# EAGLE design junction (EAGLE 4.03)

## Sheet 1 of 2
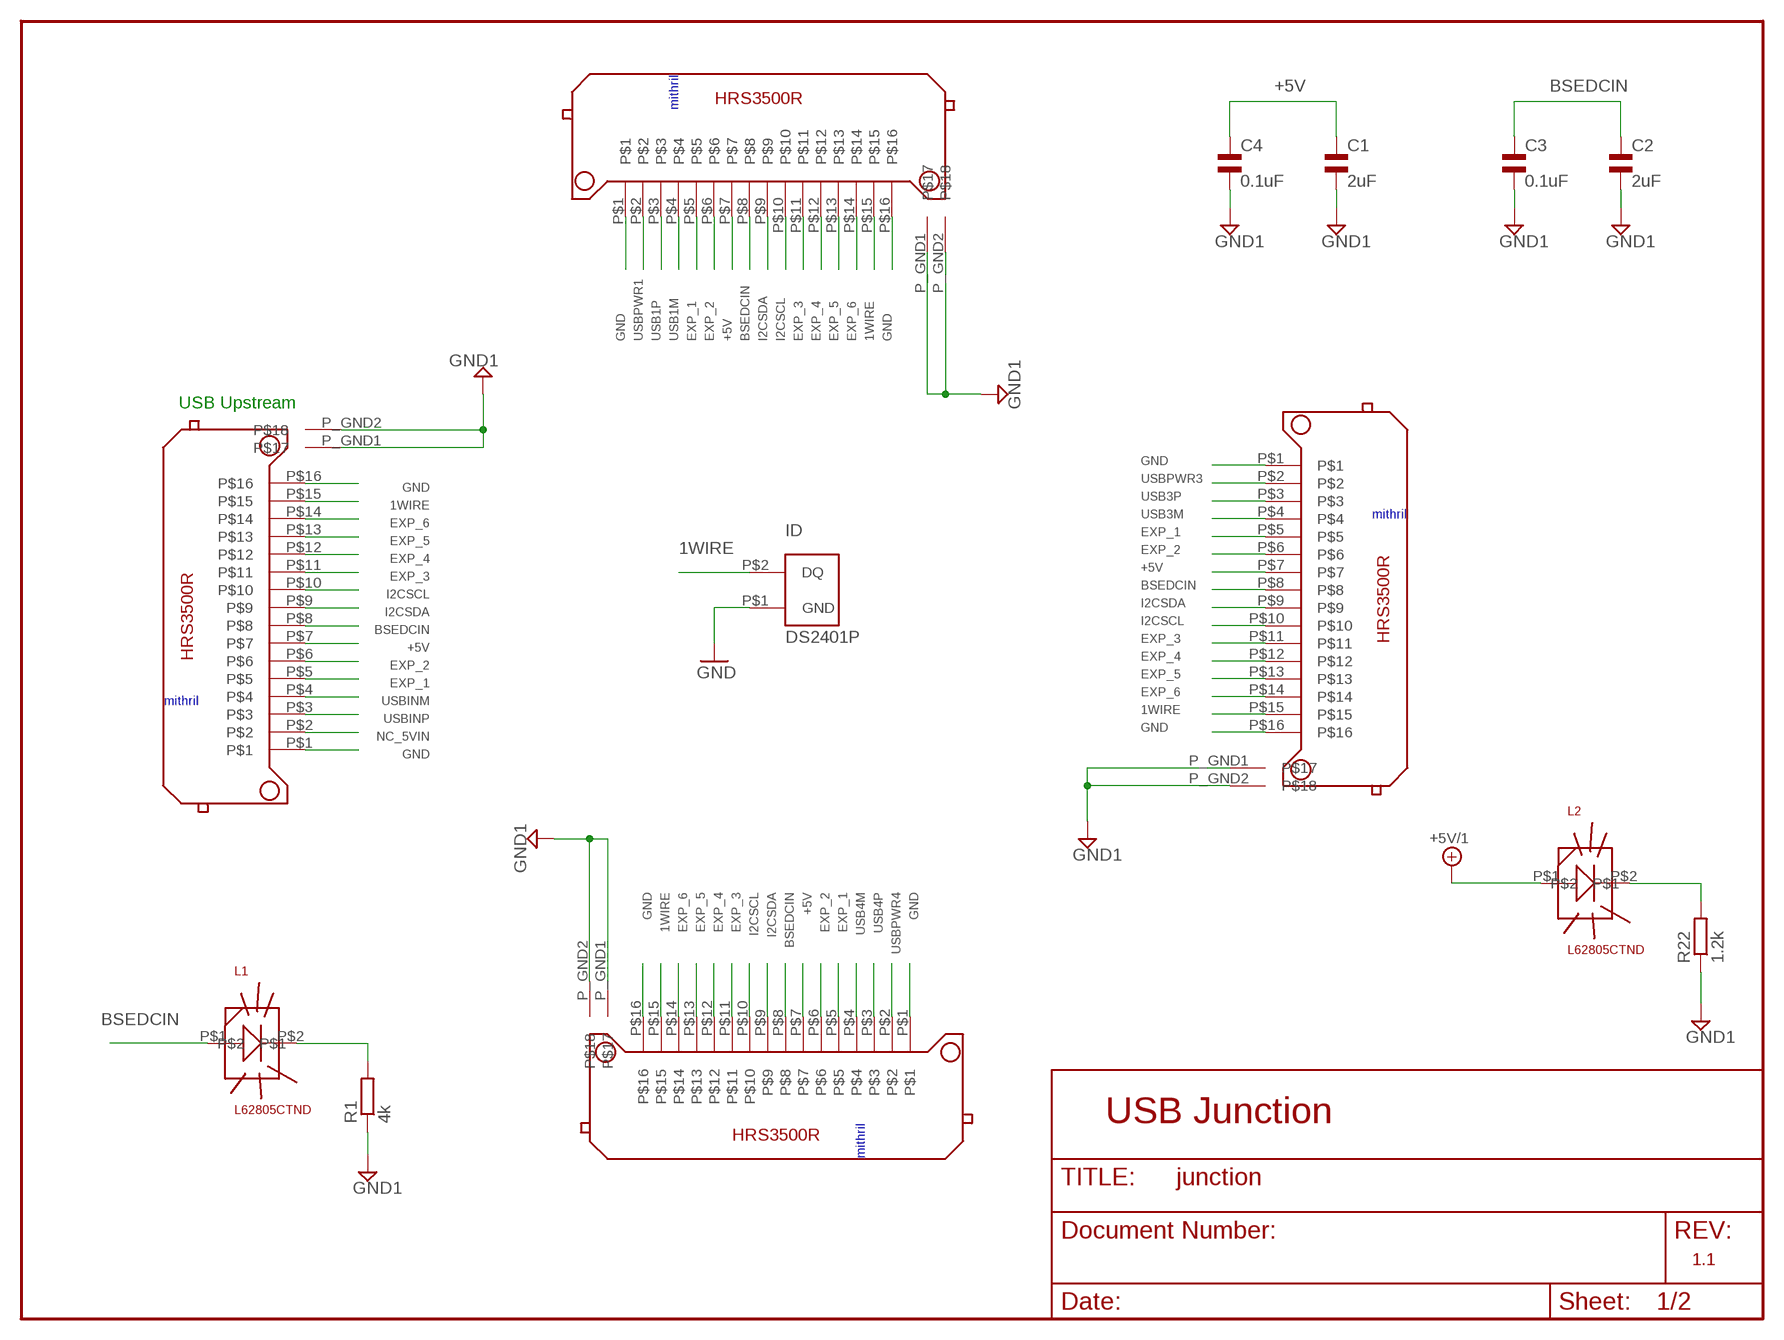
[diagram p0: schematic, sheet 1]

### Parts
C1  2uF  C1206  [C1206]
C2  2uF  C1206  [C1206]
C3  0.1uF  C1206  [C1206]
C4  0.1uF  C1206  [C1206]
ID  DS2401P  [TSOC6]
L1  L62805CTND  L62711CTND  [L62711CT]
L2  L62805CTND  L62711CTND  [L62711CT]
R1  4k  R1206  [R1206]
R22  1.2k  R1206  [R1206]
U6  HRS3500R  [HRS3500]
U7  HRS3500R  [HRS3500]
U8  HRS3500R  [HRS3500]
U9  HRS3500R  [HRS3500]

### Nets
1WIRE: ID.P$2(DQ) U6.P$15 U7.P$15 U8.P$15 U9.P$15 ; also sheet 2
+5V: C1.2 C4.2 L2.P$1 U6.P$7 U7.P$7 U8.P$7 U9.P$7 ; supply symbol labelled +5V/1 ; also sheet 2
BSEDCIN: C2.2 C3.2 L1.P$1 U6.P$8 U7.P$8 U8.P$8 U9.P$8
EXP_1: U6.P$5 U7.P$5 U8.P$5 U9.P$5
EXP_2: U6.P$6 U7.P$6 U8.P$6 U9.P$6
EXP_3: U6.P$11 U7.P$11 U8.P$11 U9.P$11
EXP_4: U6.P$12 U7.P$12 U8.P$12 U9.P$12
EXP_5: U6.P$13 U7.P$13 U8.P$13 U9.P$13
EXP_6: U6.P$14 U7.P$14 U8.P$14 U9.P$14
GND: C1.1 C2.1 C3.1 C4.1 ID.P$1(GND) R1.1 R22.1 U6.P$1 U6.P$16 U6.P_GND1 U6.P_GND2 U7.P$1 U7.P$16 U7.P_GND1 U7.P_GND2 U8.P$1 U8.P$16 U8.P_GND1 U8.P_GND2 U9.P$1 U9.P$16 U9.P_GND1 U9.P_GND2 ; supply symbol labelled GND1 ; also sheet 2
I2CSCL: U6.P$10 U7.P$10 U8.P$10 U9.P$10
I2CSDA: U6.P$9 U7.P$9 U8.P$9 U9.P$9
N$1: L1.P$2 R1.2
N$28: L2.P$2 R22.2
NC_5VIN: U6.P$2
USB1M: U7.P$4 ; also sheet 2
USB1P: U7.P$3 ; also sheet 2
USB3M: U8.P$4 ; also sheet 2
USB3P: U8.P$3 ; also sheet 2
USB4M: U9.P$4 ; also sheet 2
USB4P: U9.P$3 ; also sheet 2
USBINM: U6.P$4 ; also sheet 2
USBINP: U6.P$3 ; also sheet 2
USBPWR1: U7.P$2 ; also sheet 2
USBPWR3: U8.P$2 ; also sheet 2
USBPWR4: U9.P$2 ; also sheet 2

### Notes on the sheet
- mithril
- USB Upstream
- mithril
- mithril
- mithril | USB Junction
- 1.1

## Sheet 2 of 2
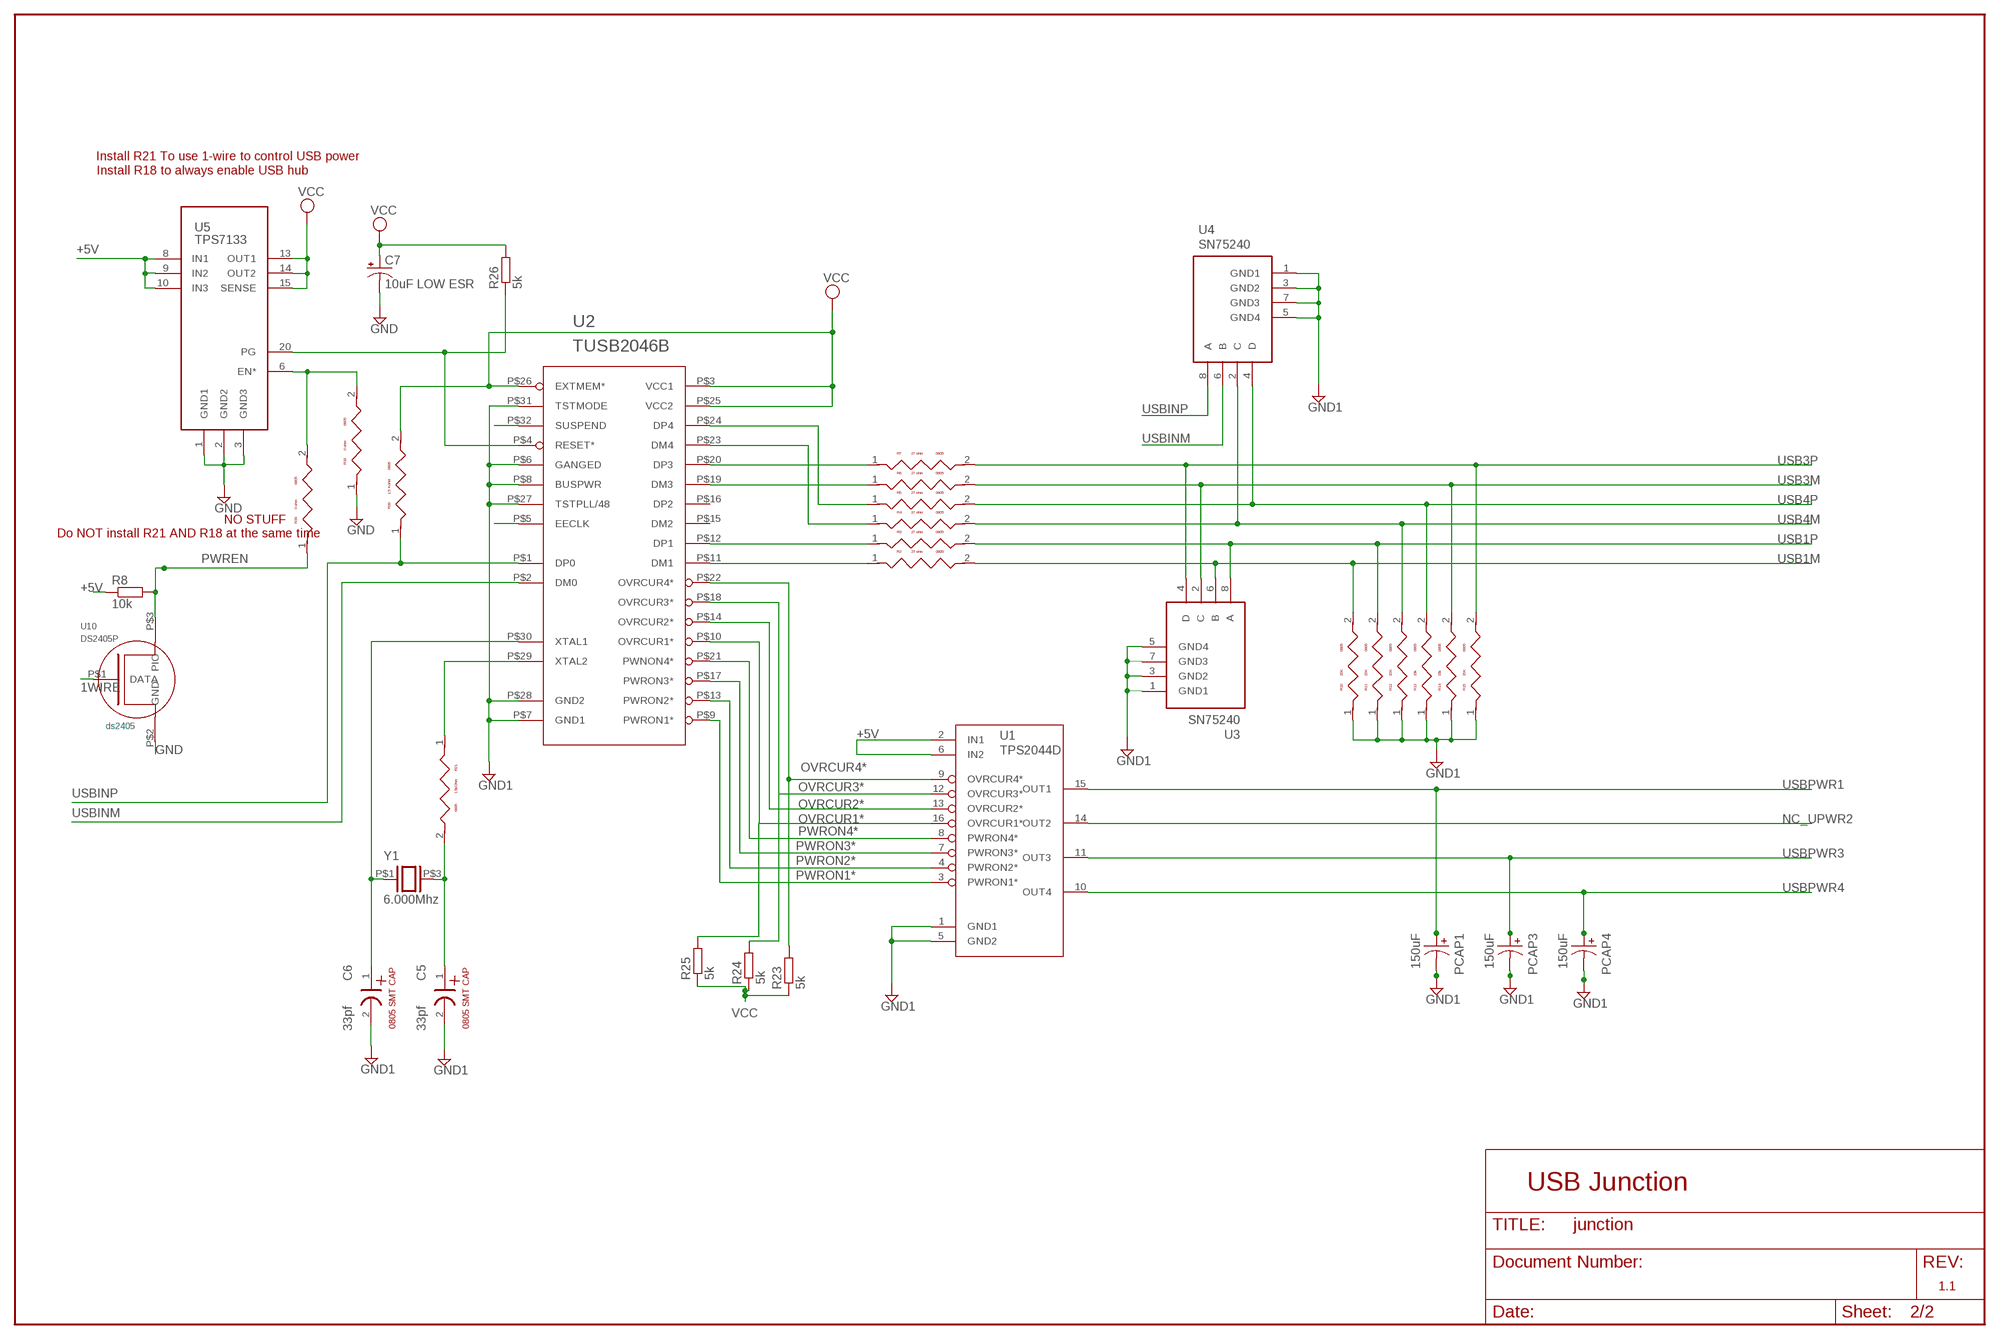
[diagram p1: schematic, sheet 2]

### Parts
C5  33pf  CAP-0805  [0805]
C6  33pf  CAP-0805  [0805]
C7  10uF LOW ESR  CPOL-USCT6032  [CT6032]
PCAP1  150uF  SPCAP0  [SPCAP]
PCAP3  150uF  SPCAP0  [SPCAP]
PCAP4  150uF  SPCAP0  [SPCAP]
R2  27 ohm  R-0805  [0805]
R3  27 ohm  R-0805  [0805]
R4  27 ohm  R-0805  [0805]
R5  27 ohm  R-0805  [0805]
R6  27 ohm  R-0805  [0805]
R7  27 ohm  R-0805  [0805]
R8  10k  R1206  [R1206]
R10  15K  R-0805@2  [0805]
R11  15K  R-0805@2  [0805]
R12  15K  R-0805@2  [0805]
R13  15k  R-0805@2  [0805]
R14  15k  R-0805@2  [0805]
R15  15K  R-0805@2  [0805]
R18  0 ohm  R-0805@2  [0805]
R19  0 ohm  R-0805@2  [0805]
R20  1.5 Kohm  R-0805@2  [0805]
R21  1.5kOhm  R-0805@2  [0805]
R23  5k  R0805  [R0805]
R24  5k  R0805  [R0805]
R25  5k  R0805  [R0805]
R26  5k  R0805  [R0805]
U1  TPS2044D  TPS2044A  [SOP-16]
U2  TUSB2046B  [TQFP-32]
U3  SN75240  [SSOP08DB]
U4  SN75240  [SSOP08DB]
U5  TPS7133  [TSSOP020]
U10  DS2405P  [TSOC6]
Y1  6.000Mhz  XTAL/SMDM505SMD  [M505]

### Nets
1WIRE: U10.P$1(DATA) ; also sheet 1
+5V: R8.1 U1.2(IN1) U1.6(IN2) U5.8(IN1) U5.9(IN2) U5.10(IN3) ; also sheet 1
GND: C5.2 C6.2 C7.- PCAP1.P$2(-) PCAP3.P$2(-) PCAP4.P$2(-) R10.1 R11.1 R12.1 R13.1 R14.1 R15.1 R18.1 U1.1(GND1) U1.5(GND2) U2.P$6(GANGED) U2.P$7(GND1) U2.P$8(BUSPWR) U2.P$27(TSTPLL/48) U2.P$28(GND2) U2.P$31(TSTMODE) U3.1(GND1) U3.3(GND2) U3.5(GND4) U3.7(GND3) U4.1(GND1) U4.3(GND2) U4.5(GND4) U4.7(GND3) U5.1(GND1) U5.2(GND2) U5.3(GND3) U10.P$2(GND) ; supply symbol labelled GND1 ; also sheet 1
N$2: R2.1 U2.P$11(DM1)
N$3: R3.1 U2.P$12(DP1)
N$6: R6.1 U2.P$19(DM3)
N$7: R7.1 U2.P$20(DP3)
N$18: R26.1 U2.P$4(RESET*) U5.20(PG)
N$20: R18.2 R19.2 U5.6(EN*)
NC_EECLK: U2.P$5(EECLK)
NC_SPND: U2.P$32(SUSPEND)
NC_UPWR2: U1.14(OUT2)
OVRCUR1*: R25.2 U1.16(OVRCUR1*) U2.P$10(OVRCUR1*)
OVRCUR2*: U1.13(OVRCUR2*) U2.P$14(OVRCUR2*)
OVRCUR3*: R24.2 U1.12(OVRCUR3*) U2.P$18(OVRCUR3*)
OVRCUR4*: R23.2 U1.9(OVRCUR4*) U2.P$22(OVRCUR4*)
PWREN: R8.2 R19.1 U10.P$3(PIO)
PWRON1*: U1.3(PWRON1*) U2.P$9(PWRON1*)
PWRON2*: U1.4(PWRON2*) U2.P$13(PWRON2*)
PWRON3*: U1.7(PWRON3*) U2.P$17(PWRON3*)
PWRON4*: U1.8(PWRON4*) U2.P$21(PWNON4*)
USB1M: R2.2 R10.2 U3.6(B) ; also sheet 1
USB1P: R3.2 R11.2 U3.8(A) ; also sheet 1
USB3M: R6.2 R14.2 U3.2(C) ; also sheet 1
USB3P: R7.2 R15.2 U3.4(D) ; also sheet 1
USB4M: R4.2 R12.2 U4.2(C) ; also sheet 1
USB4OM: R4.1 U2.P$23(DM4)
USB4P: R5.2 R13.2 U4.4(D) ; also sheet 1
USBINM: U2.P$2(DM0) U4.6(B) ; also sheet 1
USBINP: R20.1 U2.P$1(DP0) U4.8(A) ; also sheet 1
USBO4P: R5.1 U2.P$24(DP4)
USBPWR1: PCAP1.P$1(+) U1.15(OUT1) ; also sheet 1
USBPWR3: PCAP3.P$1(+) U1.11(OUT3) ; also sheet 1
USBPWR4: PCAP4.P$1(+) U1.10(OUT4) ; also sheet 1
VCC: C7.+ R20.2 R23.1 R24.1 R25.1 R26.2 U2.P$3(VCC1) U2.P$25(VCC2) U2.P$26(EXTMEM*) U5.13(OUT1) U5.14(OUT2) U5.15(SENSE)
XTAL1: C6.1 U2.P$30(XTAL1) Y1.P$1
XTAL2: R21.1 U2.P$29(XTAL2)
XTAL2_R: C5.1 R21.2 Y1.P$3
Unconnected: U2.P$15(DM2) U2.P$16(DP2)

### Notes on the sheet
- Install R21 To use 1-wire to control USB power
- Install R18 to always enable USB hub
- NO STUFF
- Do NOT install R21 AND R18 at the same time
- USB Junction
- 1.1

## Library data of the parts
C1-C4 = IPC-RCL:C1206
C5 C6 = smd:CAP-0805
C7 = rcl:CPOL-US: POLARIZED CAPACITOR, American symbol
ID = evilb0rg:DS2401P
L1 L2 = evilb0rg@2:L62711CTND
PCAP1 PCAP3 PCAP4 = evilb0rg:SPCAP: Panasonic Speciality Polymer Aluminum Electrolytic Capacitor
R1 R22 = ipc-rcl@2:R1206
R2-R7 = smd:R-0805
R8 = IPC-RCL:R1206
R10-R15 R18-R21 = smd:R-0805@2
R23-R26 = IPC-RCL:R0805
U1 = smb-junc:TPS2044A
U2 = smd:TUSB2046B
U3 U4 = smb-junc:SN75240
U5 = smb-junc:TPS7133
U6-U9 = evilb0rg:HRS3500R
U10 = evilb0rg:DS2405P
Y1 = special:XTAL/SMD

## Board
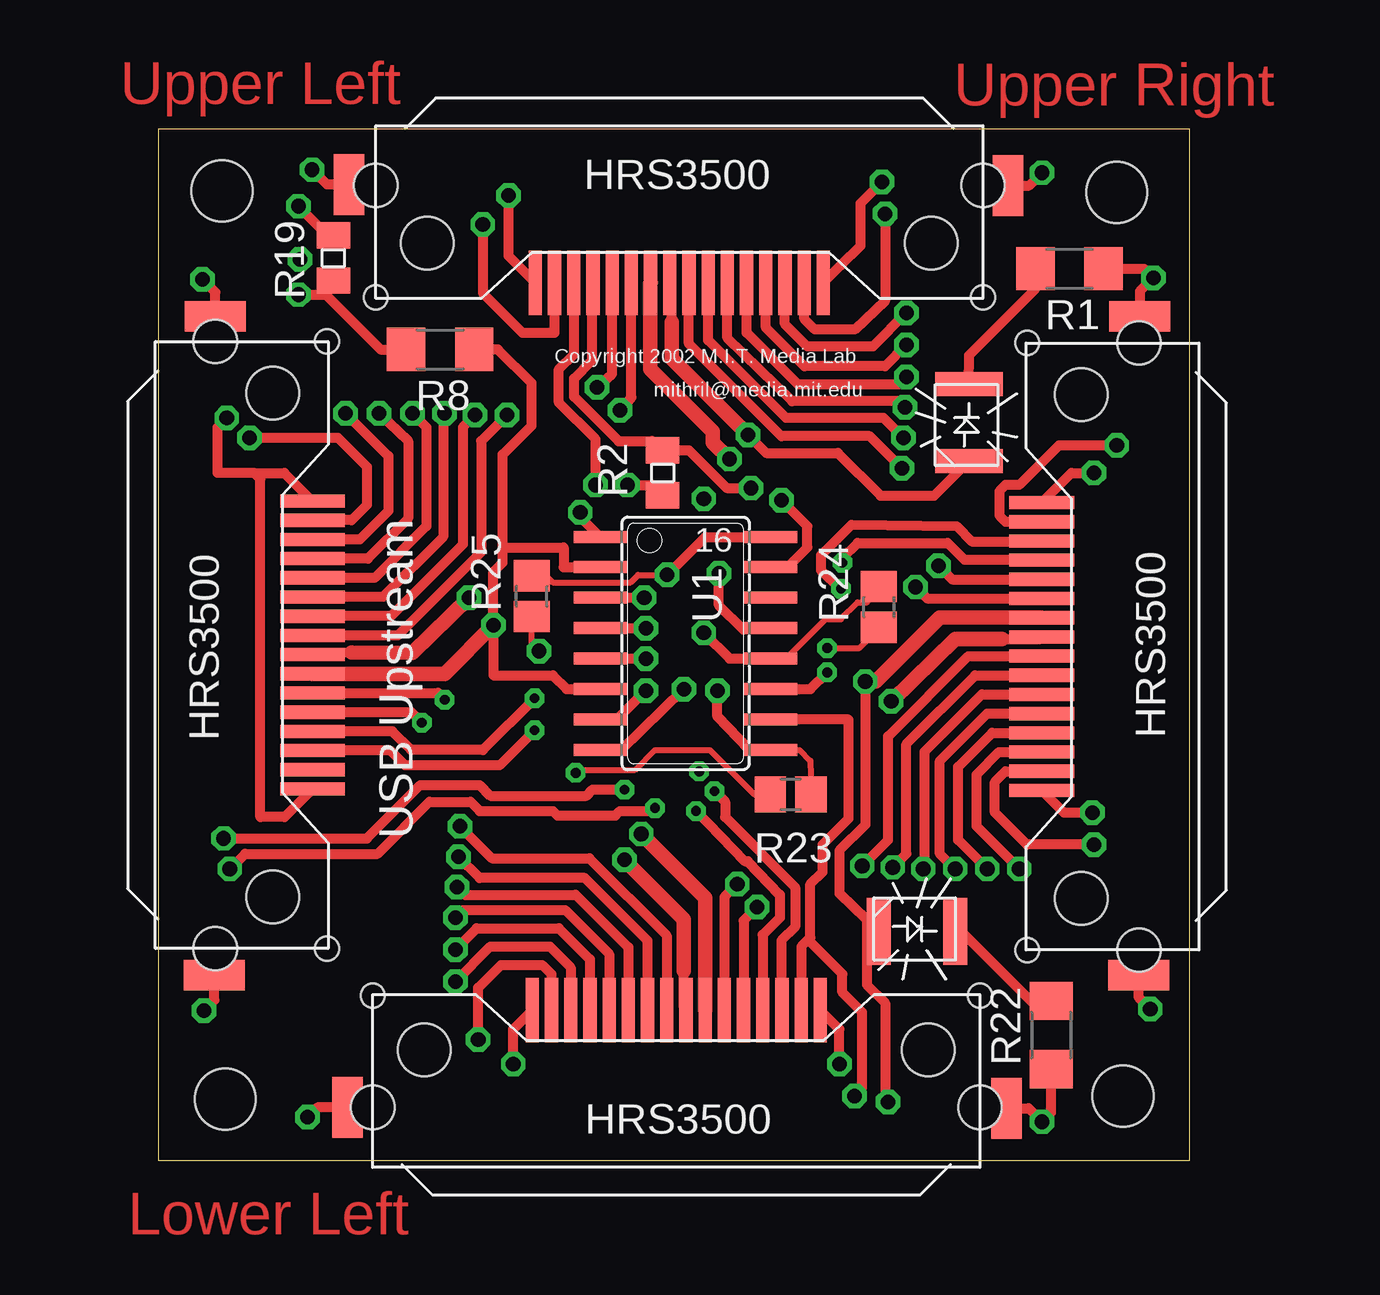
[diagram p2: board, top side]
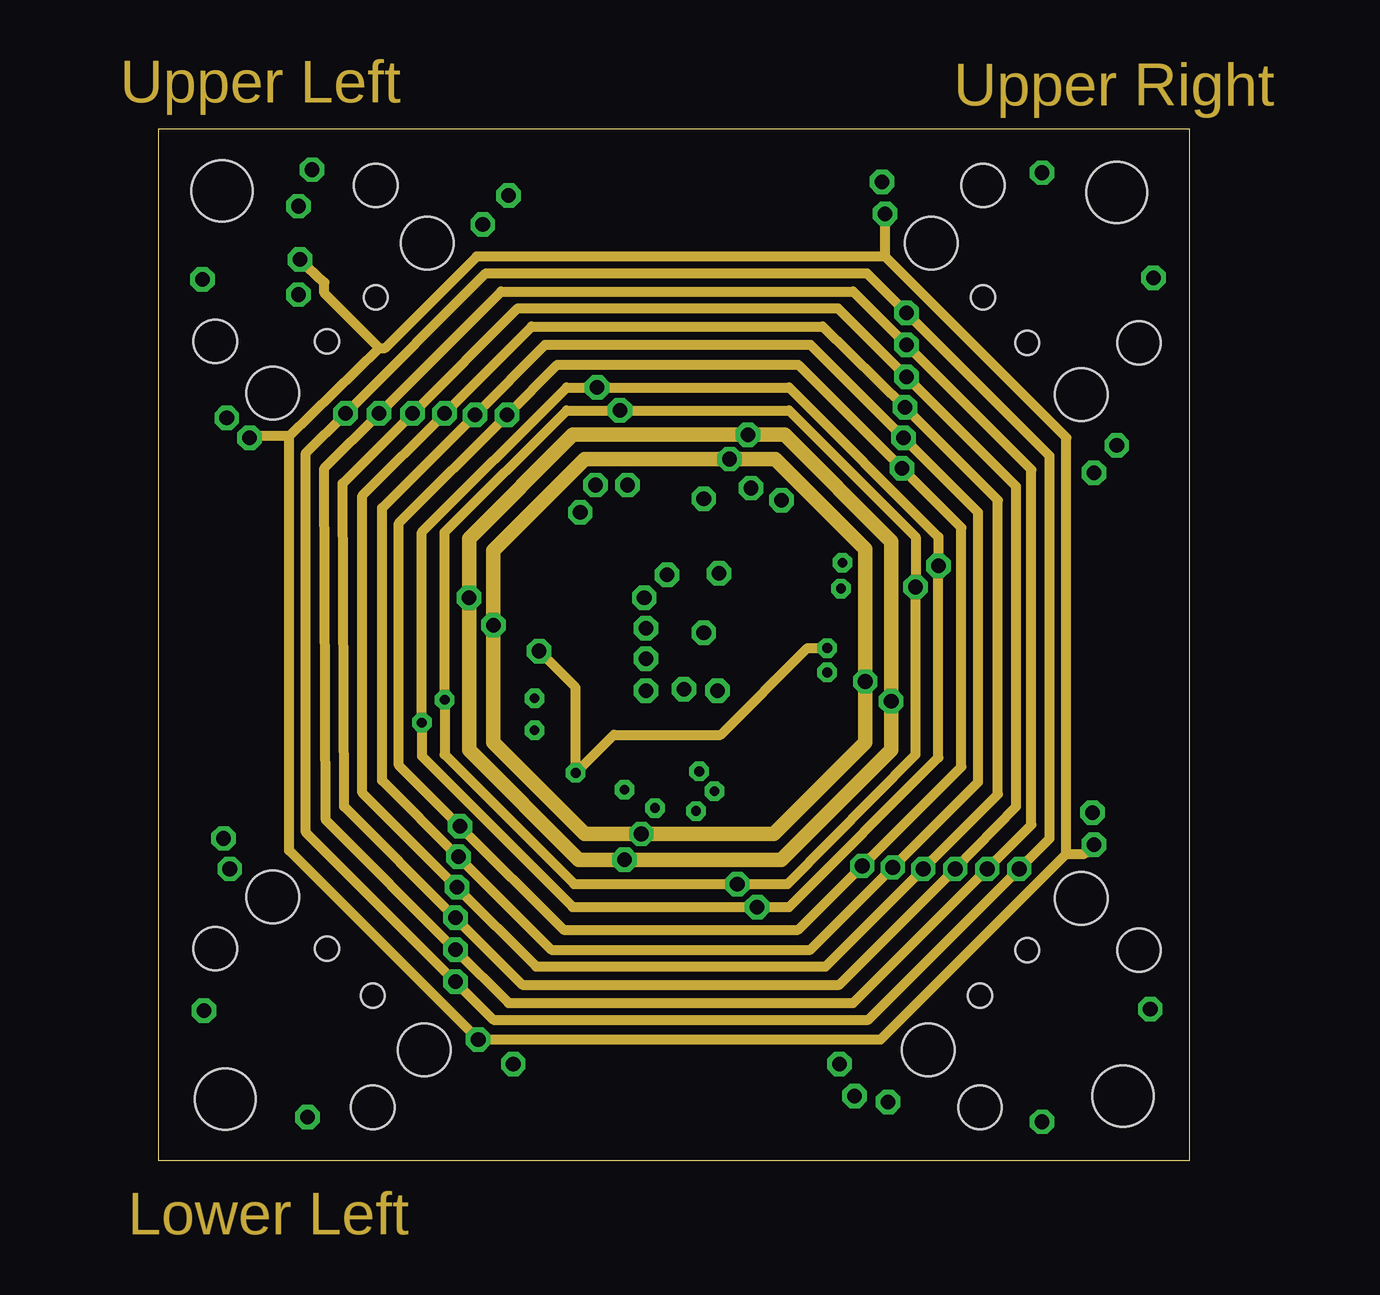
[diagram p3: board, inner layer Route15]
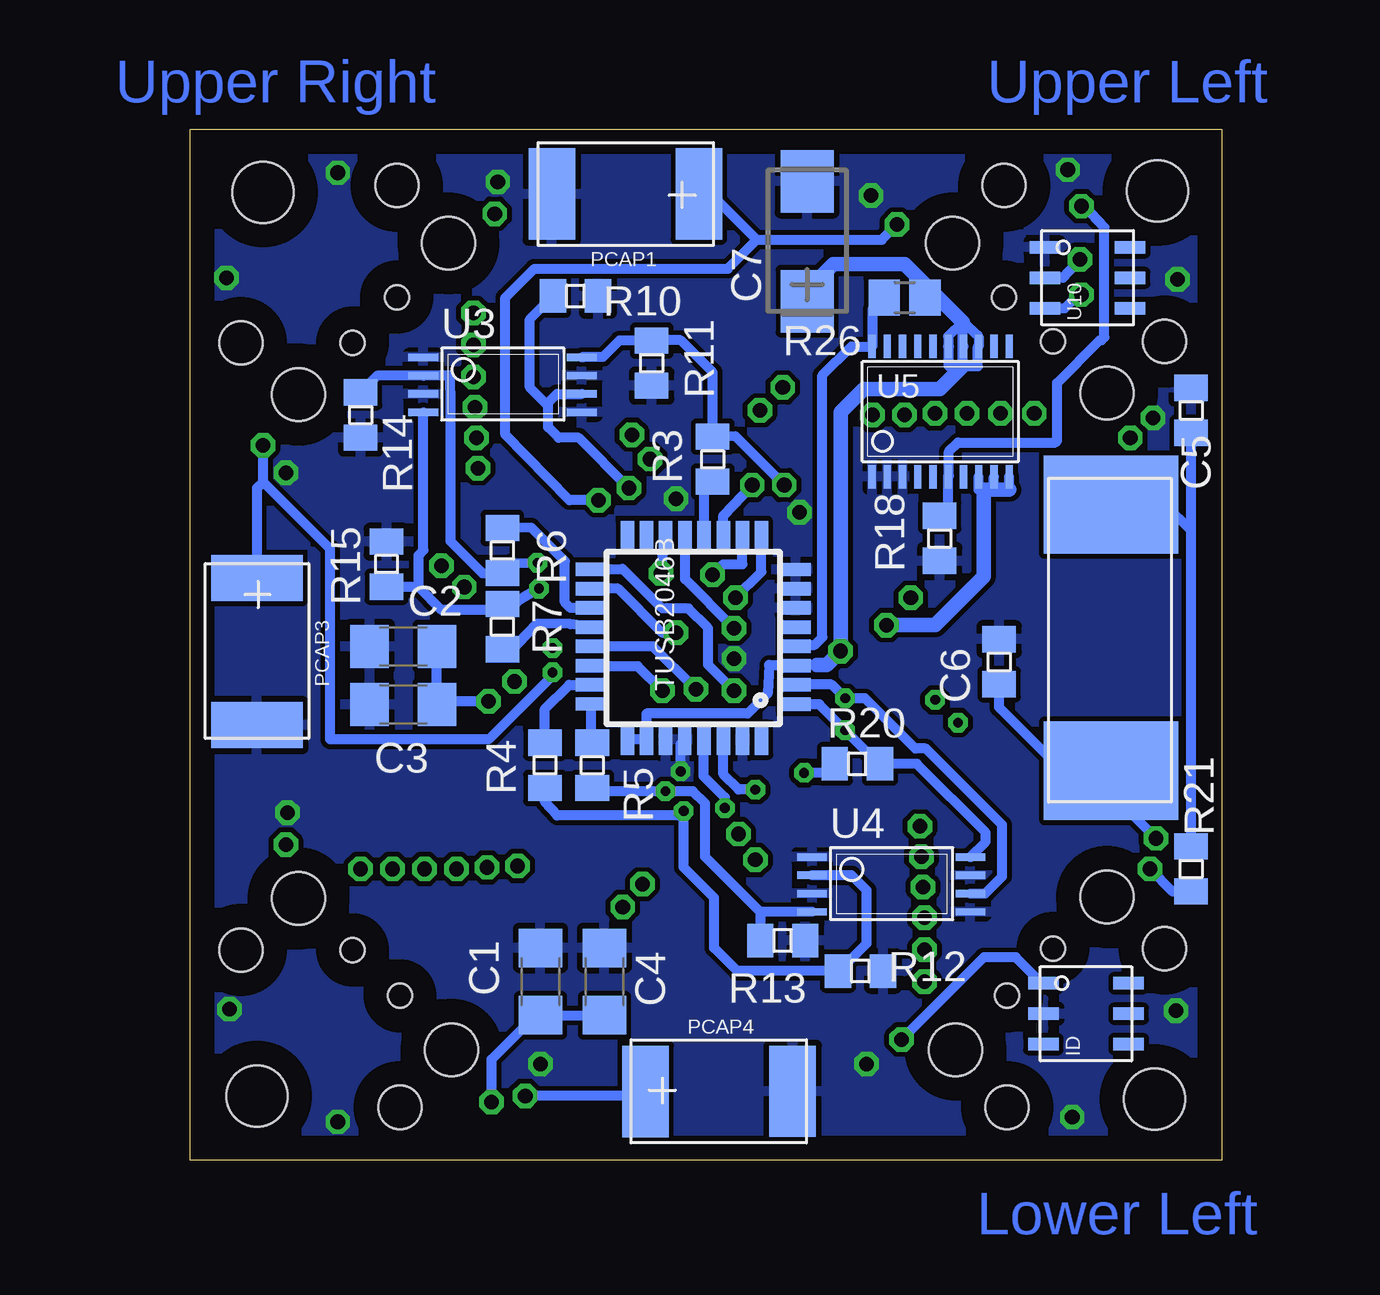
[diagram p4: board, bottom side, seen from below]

Size 42.97 x 42.98 mm. Coordinates in mm from the lower left corner, seen from the top.
Outline: 0,0 42.97,0 42.97,42.98 0,42.98 0,0
Copper layers used: Top, Route15, Bottom
Holes 2.54 mm at 2.79,2.57 40.19,2.69 39.94,40.35 2.66,40.41

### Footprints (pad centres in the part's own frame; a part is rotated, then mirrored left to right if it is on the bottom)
C1206 = smd 1.6 x 1.8: 1 -1.4,0; 2 1.4,0
0805 = smd 1.092 x 1.397: 1 -0.94,0; 2 0.94,0
CT6032 = smd 2.6 x 2.2: + -2.5,0; - 2.5,0
TSOC6 = smd 0.508 x 1.27: P$1 0,1.778; P$2 1.27,1.778; P$3 -1.27,1.778; P$4 0,-1.778; P$5 -1.27,-1.778; P$6 1.27,-1.778
L62711CT = smd 1 x 2.8: P$1 -1.6,0; P$2 1.6,0
SPCAP = smd 1.93 x 3.81: P$1 -3.047,-0.007; P$2 3.079,0
R1206 = smd 1.6 x 1.803: 1 -1.422,0; 2 1.422,0
R0805 = smd 1.3 x 1.5: 1 -0.85,0; 2 0.85,0
SOP-16 = smd 0.5 x 2.2: 1 -4.445,-3.556; 2 -3.175,-3.556; 3 -1.905,-3.556; 4 -0.635,-3.556; 5 0.635,-3.556; 6 1.905,-3.556; 7 3.175,-3.556; 8 4.445,-3.556; 9 4.445,3.556; 10 3.175,3.556; 11 1.905,3.556; 12 0.635,3.556; 13 -0.635,3.556; 14 -1.905,3.556; 15 -3.175,3.556; 16 -4.445,3.556
TQFP-32 = smd 1.27 x 0.56: P$1 4.66,-2.655; P$2 4.66,-1.85; P$3 4.66,-1.05; P$4 4.66,-0.245; P$5 4.66,0.55; P$6 4.66,1.36; P$7 4.66,2.155; P$8 4.66,2.955; P$17 -3.86,2.96; P$18 -3.86,2.155; P$19 -3.86,1.355; P$20 -3.86,0.55; P$21 -3.86,-0.245; P$22 -3.86,-1.055; P$23 -3.86,-1.85; P$24 -3.86,-2.65 | smd 0.56 x 1.27: P$9 3.24,4.34; P$10 2.45,4.34; P$11 1.65,4.34; P$12 0.855,4.34; P$13 0.055,4.34; P$14 -0.75,4.34; P$15 -1.555,4.335; P$16 -2.345,4.345; P$25 -2.34,-4.135; P$26 -1.55,-4.135; P$27 -0.75,-4.135; P$28 0.045,-4.135; P$29 0.845,-4.135; P$30 1.65,-4.135; P$31 2.455,-4.13; P$32 3.245,-4.14
SSOP08DB = smd 0.305 x 1.245: 1 -1.067,-3.48; 2 -0.305,-3.48; 3 0.457,-3.48; 4 1.219,-3.48; 5 1.219,3.124; 6 0.457,3.124; 7 -0.305,3.124; 8 -1.067,3.124
TSSOP020 = smd 0.305 x 0.991: 1 -2.819,-2.896; 2 -2.184,-2.896; 3 -1.549,-2.896; 4 -0.914,-2.896; 5 -0.279,-2.896; 6 0.356,-2.896; 7 0.991,-2.896; 8 1.626,-2.896; 9 2.261,-2.896; 10 2.896,-2.896; 11 2.896,2.54; 12 2.261,2.54; 13 1.626,2.54; 14 0.991,2.54; 15 0.356,2.54; 16 -0.279,2.54; 17 -0.914,2.54; 18 -1.549,2.54; 19 -2.184,2.54; 20 -2.819,2.54
HRS3500 = smd 0.55 x 2.7: P$1 6,1.35; P$2 5.2,1.35; P$3 4.4,1.35; P$4 3.6,1.35; P$5 2.8,1.35; P$6 2,1.35; P$7 1.2,1.35; P$8 0.4,1.35; P$9 -0.4,1.35; P$10 -1.2,1.35; P$11 -2,1.35; P$12 -2.8,1.35; P$13 -3.6,1.35; P$14 -4.4,1.35; P$15 -5.2,1.35; P$16 -6,1.35 | smd 1.27 x 2.54: P_GND1 -13.7,-2.7; P_GND2 13.76,-2.74 | hole 2.2: -10.5,-0.3; 10.5,-0.3 | hole 1.8: -12.65,-2.7; 12.65,-2.7 | hole 1: -12.65,1.95; 12.65,1.95
M505 = smd 4.1 x 5.6: P$1 5.5,-0.1; P$3 -5.6,-0.1

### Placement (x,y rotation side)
C1  28.38,7.46 270 bottom
C2  34.09,21.42 0 bottom
C3  34.09,19.01 0 bottom
C4  25.71,7.46 270 bottom
C5  1.27,31.27 90 bottom
C6  9.27,20.79 90 bottom
C7  17.27,38.32 90 bottom
ID  5.65,6.12 90 bottom
L1  33.78,30.76 90 top
L2  31.62,9.55 0 top
PCAP1  24.82,40.28 180 bottom
PCAP3  40.19,21.23 270 bottom
PCAP4  20.95,2.88 0 bottom
R1  37.97,37.17 180 top
R2  21.01,28.66 90 top
R3  21.2,29.24 90 bottom
R4  28.19,16.47 270 bottom
R5  26.22,16.47 270 bottom
R6  29.97,25.43 270 bottom
R7  29.97,22.25 90 bottom
R8  11.74,33.81 180 top
R10  26.92,36.03 180 bottom
R11  23.74,33.24 90 bottom
R12  15.04,7.9 180 bottom
R13  18.28,9.17 180 bottom
R14  35.87,31.08 90 bottom
R15  34.79,24.85 270 bottom
R18  11.74,25.93 90 bottom
R19  7.3,37.62 90 top
R20  15.17,16.54 180 bottom
R21  1.27,12.15 90 bottom
R22  37.21,5.23 90 top
R23  26.35,15.27 0 top
R24  30.03,23.08 90 top
R25  15.55,23.52 90 top
R26  13.2,35.97 0 bottom
U1  21.97,21.55 270 top
U2  22.41,21.68 0 bottom
U3  29.78,32.41 270 bottom
U4  13.58,11.58 270 bottom
U5  11.74,31.39 0 bottom
U6  5.08,21.49 270 top
U7  21.71,37.94 180 top
U8  38.16,21.42 90 top
U9  21.58,4.92 0 top
U10  5.58,36.79 90 bottom
Y1  4.5,21.74 270 bottom

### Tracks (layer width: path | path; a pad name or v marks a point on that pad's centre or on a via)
1WIRE  (via drill 0.61)
  Top 0.406: U6.P$15 8.05,26.69 8.7,27.33 8.7,28.92 7.49,30.12 v3.8,30.12 | v30.28,39.46 30.28,35.84 29.01,34.63 27.36,34.63 26.92,35.08 26.92,36.6 26.91,36.59 U7.P$15 | v38.98,13.17 36.19,13.17 34.86,14.5 34.86,15.77 35.3,16.22 36.76,16.22 36.77,16.22 U8.P$15 | v13.33,5.04 13.33,7.2 14.28,8.15 16,8.15 16.38,7.77 16.38,6.25 U9.P$15
  Route15 0.406: 5.46,30.19 9.2,33.87 | 9.2,33.87 9.46,33.87 13.27,37.68 30.28,37.68 | 30.28,37.68 37.84,30.12 37.84,12.79 | 37.84,12.79 30.09,5.04 v13.33,5.04 5.46,12.92 5.46,30.19 | v38.98,13.17 38.6,12.79 37.84,12.79 | 30.28,37.68 v30.28,39.46 | 5.46,30.19 3.87,30.19 v3.8,30.12 | 9.2,33.87 6.92,36.16 6.92,36.6 v5.9,37.55
  Bottom 0.406: ID.P$2 7.49,7.39 8.57,8.47 9.9,8.47 v13.33,5.04 | v5.9,37.55 6.6,36.79 U10.P$1
+5V  (via drill 0.61)
  Top 0.406: U1.6 17.01,19.65 16.44,20.22 13.97,20.22 v13.97,22.31 13.97,24.54 14.35,24.92 14.35,25.55 | 14.35,25.55 16.89,25.55 16.89,24.73 U1.2 | 28.38,11.13 L2.P$1 | 28.38,11.13 28.38,12.92 29.46,14 v29.46,19.96 | 28.38,11.13 28.39,11.13 29.52,10.06 29.52,7.33 30.28,6.57 30.28,2.57 v30.41,2.44 | R8.1 14.16,33.81 15.55,32.41 15.55,30.63 14.35,29.43 14.35,25.55
  Top 0.61: U6.P$7 11.93,20.29 v13.97,22.31 | U9.P$7 22.79,6.27 22.79,10.95 v20.12,13.61 | U8.P$7 36.8,22.63 32.57,22.63 29.9,19.96 v29.46,19.96 | U7.P$7 20.5,32.98 23.11,30.38 23.11,29.93 v23.81,29.24
  Route15 0.61: v13.97,22.31 13.97,25.43 17.77,29.24 v23.81,29.24 25.71,29.24 29.46,25.49 v29.46,19.96 29.46,17.42 25.65,13.61 v20.12,13.61 17.77,13.61 13.97,17.42 v13.97,22.31
  Bottom 0.406: 8.85,27.97 U5.10 | U5.8 10.12,27.97 9.9,27.97 9.48,27.97 U5.9 | v30.41,2.44 30.41,4.22 28.57,6.06 C1.2 C4.2
  Bottom 0.61: v13.97,22.31 11.93,22.31 9.9,24.35 9.9,27.97 8.85,27.97
BSEDCIN  (via drill 0.61)
  Top 0.406: 8.06,21.17 U6.P$8 | U7.P$8 21.31,36.56 21.39,36.47 21.39,34.95 | U8.P$8 36.83,21.81 36.76,21.74 35.17,21.74 | U9.P$8 21.98,6.29 21.9,6.38 21.9,7.9 | L1.P$1 32.33,27.71 30.09,27.71 28.32,29.49 25.33,29.49 v24.57,30.25
  Top 0.61: 8.06,21.17 10.58,21.15 v12.95,23.46 | v24.57,30.25 21.39,33.43 21.39,34.95 | v30.54,19.14 33.21,21.74 35.17,21.74 | v19.43,12.53 21.9,10.06 21.9,7.9
  Route15 0.61: v12.95,23.46 12.95,25.93 17.27,30.25 v24.57,30.25 26.09,30.25 30.54,25.81 v30.54,19.14 30.54,17.11 25.97,12.53 v19.43,12.53 17.52,12.53 12.95,17.11 v12.95,23.46
  Bottom 0.406: v30.54,19.14 32.51,19.14 32.63,19.01 C3.2 32.7,19.84 | 32.7,19.84 C2.2 | 32.7,19.84
EXP_1  (via drill 0.41, 0.61)
  Top 0.406: U6.P$5 10.54,18.69 v10.98,18.25 | U7.P$5 18.91,32.79 v18.28,32.22 | U8.P$5 33.07,24.22 v32.51,24.79 | U9.P$5 24.38,10 v24.95,10.57
  Route15 0.406: v10.98,18.25 10.98,26.19 17.01,32.22 v18.28,32.22 26.28,32.22 32.51,26 v32.51,24.79 32.51,16.79 26.28,10.57 v24.95,10.57 17.27,10.57 10.98,16.85 v10.98,18.25
EXP_2  (via drill 0.41, 0.61)
  Top 0.406: U6.P$6 11.65,19.49 v11.93,19.2 | U7.P$6 19.71,31.81 v19.23,31.27 | U8.P$6 32.03,23.42 v31.55,23.9 | U9.P$6 23.58,10.98 v24.12,11.52
  Route15 0.406: v11.93,19.2 11.93,26.19 17.01,31.27 v19.23,31.27 26.28,31.27 31.55,26 v31.55,23.9 31.55,16.92 26.22,11.52 v24.12,11.52 17.33,11.52 11.93,16.92 v11.93,19.2
EXP_3  (via drill 0.61)
  Top 0.406: U6.P$11 9.36,23.49 11.87,26 11.87,31.08 v11.93,31.14 | U7.P$11 23.71,34.28 26.41,31.65 30.86,31.65 v31.11,31.39 | U8.P$11 34.32,19.42 31.93,17.04 31.93,12.22 v31.87,12.15 | U9.P$11 19.58,8.88 17.39,11.07 12.76,11.07 v12.44,11.39
  Route15 0.406: v11.93,31.14 15.55,34.76 27.68,34.76 v31.11,31.39 34.98,27.52 34.98,15.27 v31.87,12.15 27.81,8.09 15.74,8.09 v12.44,11.39 8.5,15.33 8.5,27.71 v11.93,31.14
EXP_4  (via drill 0.61)
  Top 0.406: U6.P$12 9.02,24.29 11.17,26.44 11.17,30.57 v10.6,31.14 | U7.P$12 24.51,34.5 26.66,32.35 30.86,32.35 v31.17,32.66 | U8.P$12 34.53,18.63 32.57,16.66 32.57,12.79 v33.21,12.15 | U9.P$12 18.79,8.6 16.95,10.44 12.7,10.44 v12.38,10.12
  Route15 0.406: v10.6,31.14 14.98,35.52 28.32,35.52 v31.17,32.66 35.75,28.09 35.75,14.76 v33.21,12.15 28.38,7.33 15.17,7.33 v12.38,10.12 7.74,14.76 7.68,28.22 v10.6,31.14
EXP_5  (via drill 0.61)
  Top 0.406: U6.P$13 8.74,25.09 10.41,26.76 10.41,30 v9.2,31.14 | U7.P$13 25.31,34.72 26.92,33.11 30.28,33.11 v31.17,34 | U8.P$13 34.75,17.83 33.33,16.41 33.33,13.36 v34.54,12.15 | U9.P$13 17.98,8.39 16.7,9.68 13.27,9.68 v12.38,8.79
  Route15 0.406: v9.2,31.14 14.28,36.22 28.95,36.22 v31.17,34 36.38,28.79 36.38,14 v34.54,12.15 28.95,6.57 14.6,6.57 v12.38,8.79 6.98,14.19 6.92,28.85 v9.2,31.14
EXP_6  (via drill 0.61)
  Top 0.406: U6.P$14 8.4,25.89 9.58,27.08 9.58,29.36 v7.81,31.14 | U7.P$14 26.11,34.87 27.05,33.93 29.78,33.93 v31.17,35.33 | U8.P$14 35.03,17.03 34.1,16.09 34.1,13.93 v35.87,12.15 | U9.P$14 17.18,8.04 16.31,8.92 13.84,8.92 v12.38,7.45
  Route15 0.406: v7.81,31.14 13.65,36.98 29.52,36.98 v31.17,35.33 37.14,29.36 37.14,13.42 v35.87,12.15 29.59,5.87 13.97,5.87 v12.38,7.45 6.15,13.68 6.15,29.49 v7.81,31.14
GND  (via drill 0.41, 0.61)
  Top 0.406: U6.P_GND2 2.33,6.68 v1.9,6.25 | U9.P_GND1 6.63,2.21 v6.22,1.8 | U8.P$1 38.05,28.66 v38.98,28.66 | U8.P$16 37.73,14.5 v38.92,14.5 | U8.P_GND1 40.86,6.79 v41.33,6.31 | U9.P_GND2 36.26,2.17 v36.83,1.61 37.21,1.99 R22.1 | U9.P$1 28.38,5.47 v28.38,4.03 | U1.5 v20.31,20.92 | U8.P_GND2 40.9,36.23 v41.46,36.79 41.08,37.17 R1.1 | U7.P_GND1 36.29,40.64 v36.83,41.17 | U7.P$16 28.44,37.32 29.27,38.13 29.27,39.9 v30.16,40.79 | U7.P$1 14.6,37.7 v14.6,40.22 | U7.P_GND2 7.03,40.68 v6.41,41.3 | U6.P_GND1 2.38,36.19 v1.84,36.73 | U9.P$16 14.79,5.47 v14.79,4.03 | U6.P$16 5.25,28.66 4,28.66 | 4,28.66 2.47,28.66 2.47,30.57 v2.85,30.95 | 4,28.66 4.25,28.41 4.25,14.31 5.27,14.31 6.42,15.47 U6.P$1 | U1.1 17.58,26.82 v17.58,27.01
  Bottom 0.406: 22.35,17.54 22.35,17.55 | 22.35,17.54 U2.P$28 | v22.54,16.22 22.54,17.36 22.35,17.54
  other vias: 22.73,27.58
  pour Bottom: 0.25,42.7 0.25,0.28 42.73,0.28 42.73,42.7
I2CSCL  (via drill 0.61)
  Top 0.406: U6.P$10 9.7,22.69 12.7,25.68 12.7,30.57 v13.2,31.08 | U9.P$10 20.38,9.16 17.77,11.77 13.39,11.77 v12.5,12.66 | U8.P$10 34.04,20.22 31.17,17.36 31.17,12.79 v30.6,12.22 | U7.P$10 22.91,34.19 26.16,30.95 30.22,30.95 v31.05,30.12
  Route15 0.406: v13.2,31.08 16.12,34 27.17,34 v31.05,30.12 34.16,27.01 34.16,15.77 v30.6,12.22 27.17,8.79 16.38,8.79 v12.5,12.66 9.33,15.84 9.33,27.2 v13.2,31.08
I2CSDA  (via drill 0.61)
  Top 0.406: U6.P$9 9.98,21.89 13.46,25.36 13.46,30 v14.54,31.08 | U9.P$9 21.18,9.38 17.96,12.6 13.9,12.6 v12.57,13.93 | U7.P$9 22.11,34.04 25.97,30.19 29.65,30.19 v30.98,28.85 | U8.P$9 33.76,21.03 30.41,17.68 30.41,13.36 v29.33,12.28
  Route15 0.406: v14.54,31.08 16.63,33.17 26.66,33.17 v30.98,28.85 33.46,26.38 33.46,16.41 v29.33,12.28 26.66,9.61 16.89,9.61 v12.57,13.93 10.03,16.47 10.03,26.57 v14.54,31.08
N$1
  Top 0.406: L1.P$2 33.79,33.57 36.51,36.28 36.51,37.11 36.55,37.15 R1.2
N$2  (via drill 0.61)
  Top 0.406: R2.1 20.57,28.16 v19.55,28.16
  Bottom 0.406: U2.P$11 20.76,26.88 v19.55,28.16
N$3
  Bottom 0.406: U2.P$12 21.55,27.11 21.55,27.94 21.2,28.28 R3.1
N$6
  Bottom 0.406: U2.P$19 27.13,23.03 27.36,23.27 27.36,24.98 28.76,26.38 R6.1
N$7
  Bottom 0.406: U2.P$20 27.13,22.36 28.51,22.38 29.71,21.11 29.92,21.31 R7.1
N$18
  Bottom 0.406: U2.P$4 17.69,21.46 17.71,21.49 16.95,21.49 16.63,21.81 16.63,32.73 15.43,33.93 U5.20 14.54,33.96 14.54,35.48 R26.1
N$20  (via drill 0.61)
  Top 0.406: R19.2 7.06,38.56 v5.84,39.78
  Bottom 0.406: R18.2 11.74,26.89 11.39,27.24 U5.6 11.36,28.54 11.36,29.55 10.98,29.93 6.92,29.93 6.85,30 6.85,32.41 5.08,34.19 5.01,34.19 4.88,34.32 4.88,38.89 5.71,39.78 v5.84,39.78
N$28
  Top 0.406: L2.P$2 33.46,9.55 36.38,6.63 37.21,6.63 R22.2
OVRCUR1*  (via drill 0.61)
  Top 0.254: R25.2 16.16,24.37 16.44,24.09 19.68,24.09 20,24.41 v21.2,24.41
  Top 0.406: v21.2,24.41 22.79,26 U1.16
  Bottom 0.406: 19.96,26.03 U2.P$10 19.96,24.85 20.76,24.85 v21.2,24.41
OVRCUR2*  (via drill 0.61)
  Top 0.406: U1.13 24.38,22.12 23.36,23.14 v23.36,24.47
  Bottom 0.406: U2.P$14 23.17,26.02 v23.36,24.47
OVRCUR3*  (via drill 0.61)
  Top 0.254: R24.2 29.99,23.93 29.52,23.27 29.14,23.27 28.44,22.57 27.81,22.57 26.16,20.92 U1.12
  Top 0.406: U1.12 23.81,20.92 v22.73,22
  Bottom 0.406: v22.73,22 23.3,22 25.14,23.84 26.16,23.84 26.16,23.83 U2.P$18
OVRCUR4*  (via drill 0.61)
  Top 0.254: R23.2 27.2,15.43 27.17,16.66 26.73,17.11 U1.9
  Top 0.406: U1.9 24.63,17.11 23.3,18.5 v23.3,19.58
  Bottom 0.406: U2.P$22 26.18,20.6 24.32,20.6 v23.3,19.58
PWREN  (via drill 0.61)
  Top 0.406: R8.2 9.27,33.81 6.98,36.09 | v5.84,36.09 6.98,36.09 | R19.1 7.11,36.6 6.98,36.47 6.98,36.09
  Bottom 0.406: v5.84,36.09 5.96,36.09 6.54,35.52 U10.P$3
PWRON1*  (via drill 0.61)
  Top 0.406: U1.3 v20.25,23.46
  Bottom 0.406: U2.P$9 19.17,24.54 v20.25,23.46
PWRON2*  (via drill 0.61)
  Top 0.406: U1.4 v20.31,22.19
  Bottom 0.406: U2.P$13 22.36,24.23 v20.31,22.19
PWRON3*  (via drill 0.61)
  Top 0.406: v20.31,19.58 19.11,18.38 U1.7
  Bottom 0.406: v20.31,19.58 21.39,20.66 21.39,22.19 22.22,23.01 23.3,23.01 24.95,24.66 24.95,24.64 U2.P$17
PWRON4*  (via drill 0.61)
  Top 0.406: v21.9,19.65 19.3,17.11 U1.8
  Bottom 0.406: U2.P$21 23.69,21.43 v21.9,19.65
USB1M  (via drill 0.61)
  Top 0.406: U7.P$4 18.09,36.6 18.09,33.36 17.33,32.6 17.33,31.84 19.18,29.98 20.57,30 20.58,30 R2.2 22.11,29.6 23.68,28.03 v24.7,28.03
  Bottom 0.406: v24.7,28.03 26.79,30.12 27.62,30.12 28.06,30.57 28.06,31.58 | R10.2 28.82,35.06 28.82,32.22 28.19,31.58 28.06,31.58 | U3.6 27.69,31.95 28.06,31.58
USB1P  (via drill 0.61)
  Top 0.406: v18.22,28.16 18.22,30.06 16.7,31.58 16.7,32.98 17.33,33.62 17.33,36.54 17.31,36.56 U7.P$3
  Bottom 0.406: v18.22,28.16 20.25,30.19 R3.2 21.2,32.85 22.54,34.19 R11.2 25.09,34.18 25.78,33.49 26.6,33.49 26.61,33.48 U3.8
USB3M  (via drill 0.41)
  Top 0.406: v28.51,24.92 28.51,25.11 29.14,25.74 32.89,25.74 33.59,25.04 36.83,25.04 U8.P$4
  Bottom 0.406: v28.51,24.92 29.57,24.9 R6.2 29.97,24.47 30.79,24.47 32.13,25.81 32.13,31.46 32.14,32.72 U3.2 35.19,32.72 R14.2
USB3P  (via drill 0.41)
  Top 0.406: v28.44,23.84 27.62,24.6 27.62,25.24 28.89,26.51 33.27,26.44 33.9,25.81 36.79,25.81 U8.P$3
  Bottom 0.406: v28.44,23.84 29.33,23.33 29.71,22.95 29.73,22.95 R7.2 29.97,23.2 30.22,22.95 32.51,22.95 33.46,23.9 | U3.4 33.26,25.44 33.46,25.24 33.46,23.9 | R15.2 33.46,23.9
USB4M  (via drill 0.41)
  Top 0.406: U9.P$4 25.18,9.4 25.9,10.12 25.9,11.07 24.57,12.47 24.44,12.47 v22.41,14.57
  Bottom 0.406: R4.2 28.19,14.95 27.68,14.38 22.6,14.38 v22.41,14.57 22.41,12.22 21.14,10.95 21.14,8.85 20.19,7.9 16,7.9 | U4.2 15.41,11.89 14.79,11.27 14.79,9.04 15.93,7.9 16,7.9 | 16,7.9 R12.2
USB4OM
  Bottom 0.406: U2.P$23 27.18,19.83 28.19,18.82 R4.1
USB4P  (via drill 0.41)
  Top 0.406: v23.17,15.39 23.62,14.95 23.62,14.31 26.54,11.39 26.54,9.74 25.97,9.17 25.97,6.31 25.98,6.29 U9.P$3
  Bottom 0.406: R5.2 26.23,15.52 R5.2 26.09,15.39 v23.17,15.39 22.03,15.39 21.52,14.88 21.52,12.66 19.22,10.36 | U4.4 19.22,10.36 | R13.2 19.23,9.17 19.22,9.18 19.22,10.36
USBINM  (via drill 0.41)
  Top 0.406: U6.P$4 9.75,17.89 10.54,17.11 13.52,17.11 v15.68,19.27
  Bottom 0.406: U2.P$2 17.68,19.84 16.25,19.84 v15.68,19.27 14.85,19.27 12.76,17.17 12.31,17.17 9.14,14 9.14,11.84 9.85,11.13 U4.6
USBINP  (via drill 0.41)
  Top 0.406: U6.P$3 9.67,17.09 10.28,16.47 14.22,16.47 v15.68,17.93
  Bottom 0.406: U2.P$1 17.68,19.01 16.76,19.01 v15.68,17.93 14.68,16.93 R20.1 12.7,16.54 9.83,13.67 9.83,13.28 U4.8
USBO4P
  Bottom 0.406: R5.1 26.22,17.36 26.27,17.36 U2.P$24
USBPWR1  (via drill 0.61)
  Top 0.406: U1.15 26.22,24.73 27.05,25.55 27.05,26.44 v25.97,27.52 | U7.P$2 16.51,34.5 15.17,34.51 13.52,36.16 v13.52,39.01
  Bottom 0.406: v25.97,27.52 27.17,27.52 29.84,30.25 29.84,35.97 28.63,37.17 20.57,37.17 19.36,38.38 | 19.36,38.38 14.16,38.38 v13.52,39.01 | PCAP1.P$1 21.27,40.28 19.36,38.38
USBPWR3  (via drill 0.41, 0.61)
  Top 0.406: U1.11 27.17,19.65 v27.87,20.35 | U8.P$2 36.82,26.63 | 36.76,26.63 36.77,26.63 U8.P$2 | v39.94,29.81 37.52,29.81 35.87,28.16 35.3,28.16 35.05,27.9 35.05,26.89 35.3,26.63 36.83,26.63 U8.P$2
  Bottom 0.406: v27.87,20.35 27.87,20.22 30.54,17.55 37.14,17.55 37.14,25.49 39.94,28.28 | 39.94,28.28 v39.94,29.81 | PCAP3.P$1 40.19,28.03 39.94,28.28
USBPWR4  (via drill 0.61)
  Top 0.406: U1.10 28.76,18.38 28.76,14.25 27.68,13.17 27.68,12.03 27.17,11.52 27.17,9.3 | 27.17,9.3 26.79,8.92 26.79,6.31 U9.P$2 | v29.01,2.69 29.33,3.01 29.33,6.19 28.51,7.01 28.51,7.77 27.17,9.11 27.17,9.3
  Bottom 0.406: PCAP4.P$1 23.87,2.71 23.87,2.69 v29.01,2.69
VCC  (via drill 0.41, 0.61)
  Top 0.254: R25.1 15.55,21.55 v15.87,21.23 | R24.1 30.03,22.19 29.2,21.36 v27.87,21.36 | R23.1 24.82,15.27 22.98,17.11 20.7,17.11 19.87,16.28 17.52,16.28 v17.39,16.15
  Route15 0.406: v15.87,21.23 17.39,19.71 v17.39,16.15 18.98,17.74 23.43,17.74 27.05,21.36 v27.87,21.36
  Bottom 0.406: U2.P$26 U2.P$25 | U2.P$26 23.88,17.54 23.87,17.55 | U2.P$26 23.96,18.63 19.74,18.63 18.92,19.46 18.85,20.63 | 10.79,33.93 U5.14 | 10.79,33.93 10.79,34.95 | U5.15 11.39,34.35 10.79,34.95 | U5.13 10.12,34.34 10.79,34.95 | 10.79,33.11 11.36,33.11 11.36,33.93 | 10.79,33.11 10.16,33.11 10.16,33.93 | 10.79,33.11 10.79,33.93 | 16.86,20.66 17.65,20.66 17.65,20.63 U2.P$3 18.85,20.63 | 18.85,20.63 18.85,20.66 | R20.2 16.56,16.15 v17.39,16.15 | R26.2 12.8,36.32 12.82,36.98
  Bottom 0.61: C7.+ 17.27,36.28 16.19,37.36 13.2,37.36 12.82,36.98 10.79,34.95 | 16.86,20.66 16.44,20.66 v15.87,21.23 15.87,31.2 14.92,32.16 11.74,32.16 10.79,33.11
XTAL1  (via drill 0.41, 0.61)
  Top 0.406: v19.43,15.46 18.09,15.46 17.84,15.2 13.84,15.2 13.39,15.65 10.92,15.65 8.7,13.42 v2.73,13.42
  Bottom 0.406: U2.P$30 20.76,16.09 20.12,15.46 v19.43,15.46 | v2.73,13.42 4.57,15.27 4.57,15.96 4.58,15.96 Y1.P$1 4.61,15.99 4.63,15.96 6.34,15.96 9.27,18.88 C6.1
XTAL2  (via drill 0.41, 0.61)
  Top 0.406: v20.7,14.69 20.57,14.57 19.23,14.57 19.04,14.38 16.63,14.38 16.44,14.57 13.39,14.57 13.01,14.95 11.3,14.95 9.14,12.79 3.61,12.79 v2.98,12.15
  Bottom 0.406: 21.57,16.01 U2.P$29 | v20.7,14.69 20.7,15.14 21.57,16.01 | 21.57,16.01 21.58,16.03 | R21.1 1.32,11.21 2.03,11.2 v2.98,12.15
XTAL2_R
  Bottom 0.406: Y1.P$3 2.36,27.34 1.27,26.25 | 1.27,30.38 C5.1 1.27,26.25 | R21.2 1.27,26.25

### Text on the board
Top: Upper Left | Upper Right | Lower Left
$GND: Upper Left | Upper Right | Lower Left
Route15: Upper Left | Upper Right | Lower Left
Bottom: Upper Left | Upper Right | Lower Left
tPlace: Copyright 2002 M.I.T. Media Lab | mithril@media.mit.edu
tNames: USB Upstream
